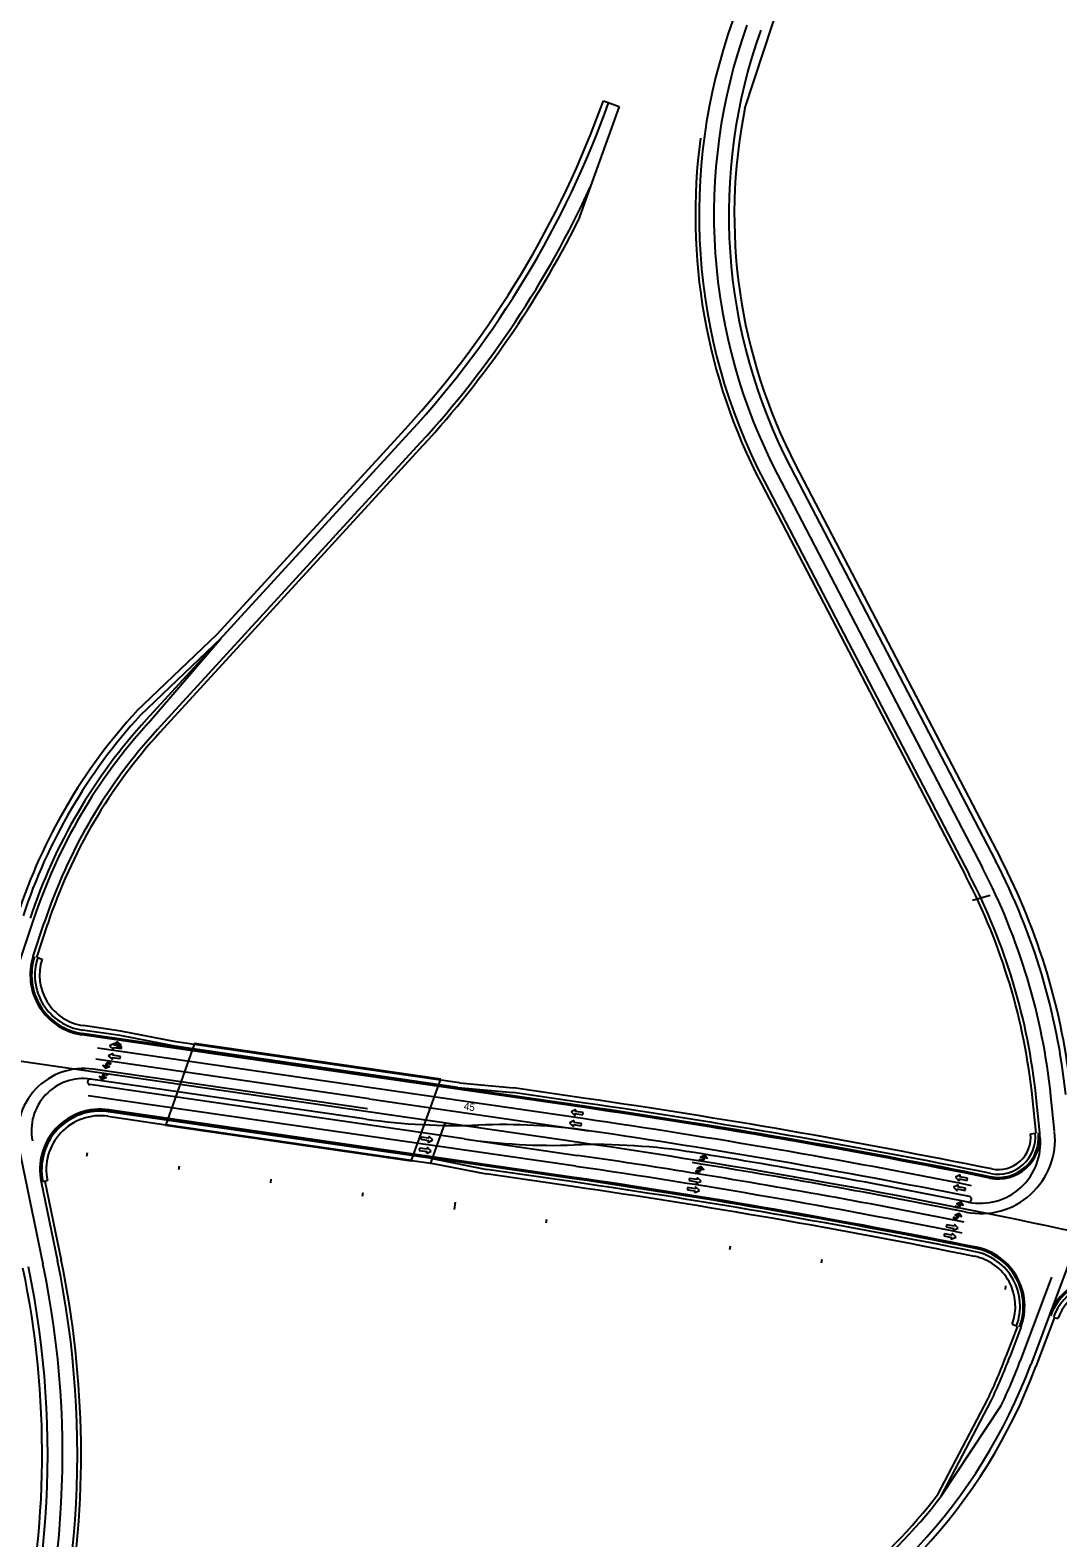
# Model space of a CAD drawing. Extents: x 1936748 to 1944587, y 778690 to 782840.
# Drawn here: x 1940638 to 1941746, y 780074 to 781699 of the extents above; entities that cross this region are included whole.
import ezdxf

# ---------------------------------------------------------------- set-up
doc = ezdxf.new("R2010")
doc.units = 0
for name, color, linetype in [('Default', 7, 'Continuous'), ('RD_HC_CL_Rel', 7, 'Continuous'), ('RD_HC_Data_Tic', 7, 'Continuous'), ('RD_HC_TX_Sta50', 7, 'Continuous'), ('RD_PD_ALT1_LnLine', 7, 'Continuous'), ('RD_PD_ALT3_LnLine', 7, 'Continuous'), ('RD_PD_Bridge', 7, 'Continuous'), ('RD_PD_Final_TrvlWay', 7, 'Continuous'), ('RD_PD_FOC', 7, 'Continuous'), ('RD_PD_PaveShd', 7, 'Continuous'), ('RD_PD_SW', 7, 'Continuous')]:
    doc.layers.add(name, color=color, linetype=linetype)

msp = doc.modelspace()

# ---------------------------------------------------------------- linework, layer by layer
at = {"layer": 'Default'}
for p, q in [((1940728.4, 780606.8), (1940723.9, 780604.6)), ((1940723.9, 780604.6), (1940727.5, 780601.2)), ((1940728.3, 780601.5), (1940728.1, 780602.8)), ((1940728.1, 780602.8), (1940736.6, 780601.6)), ((1940728.4, 780606.8), (1940728.4, 780606.8)), ((1940728.5, 780605.1), (1940728.9, 780606.3)), ((1940736.9, 780603.9), (1940728.5, 780605.1)), ((1940735.3, 780602.9), (1940736.6, 780602.8)), ((1940736.6, 780601.6), (1940736.9, 780603.9)), ((1940727.1, 780596), (1940722.6, 780593.8)), ((1940722.6, 780593.8), (1940726.3, 780590.4)), ((1940723.9, 780585.1), (1940725.2, 780584.9)), ((1940727, 780590.8), (1940726.9, 780592)), ((1940726.9, 780592), (1940735.3, 780590.8)), ((1940727.1, 780596), (1940727.1, 780596)), ((1940727.2, 780594.3), (1940727.7, 780595.5)), ((1940735.6, 780593.1), (1940727.2, 780594.3)), ((1940735.3, 780590.8), (1940735.6, 780593.1)), ((1940720.2, 780573.2), (1940721.6, 780573)), ((1941225.7, 780535.5), (1941221.3, 780533.3)), ((1941225.7, 780535.5), (1941225.7, 780535.5)), ((1941224, 780523.6), (1941219.5, 780521.4)), ((1941219.5, 780521.4), (1941223.2, 780518)), ((1941221.3, 780533.3), (1941224.9, 780529.9)), ((1941223.9, 780518.4), (1941223.8, 780519.6)), ((1941223.8, 780519.6), (1941232.2, 780518.4)), ((1941224, 780523.6), (1941224, 780523.6)), ((1941224.1, 780521.9), (1941224.6, 780523.1)), ((1941232.5, 780520.7), (1941224.1, 780521.9)), ((1941225.6, 780530.2), (1941225.5, 780531.5)), ((1941225.5, 780531.5), (1941233.9, 780530.3)), ((1941225.8, 780533.8), (1941226.3, 780535)), ((1941234.3, 780532.6), (1941225.8, 780533.8)), ((1941232.2, 780518.4), (1941232.5, 780520.7)), ((1941233.9, 780530.3), (1941234.3, 780532.6)), ((1941059.7, 780506.1), (1941059.4, 780503.8)), ((1941059.4, 780503.8), (1941067.8, 780502.6)), ((1941068.1, 780504.9), (1941059.7, 780506.1)), ((1941067.9, 780500.8), (1941072.4, 780503.1)), ((1941068, 780506.1), (1941068.1, 780504.9)), ((1941072.4, 780503.1), (1941068.7, 780506.5)), ((1941058, 780494.2), (1941057.6, 780491.9)), ((1941057.6, 780491.9), (1941066.1, 780490.7)), ((1941066.4, 780493), (1941058, 780494.2)), ((1941066.1, 780490.7), (1941065.6, 780489.5)), ((1941066.2, 780489), (1941070.6, 780491.2)), ((1941066.2, 780489), (1941066.2, 780489)), ((1941066.3, 780494.2), (1941066.4, 780493)), ((1941070.6, 780491.2), (1941067, 780494.6)), ((1941067.8, 780502.6), (1941067.3, 780501.4)), ((1941067.9, 780500.8), (1941067.9, 780500.8)), ((1941360.9, 780481.7), (1941359.5, 780481.9)), ((1941348.7, 780461.6), (1941348.4, 780459.3)), ((1941348.4, 780459.3), (1941356.8, 780458.1)), ((1941357.2, 780460.4), (1941348.7, 780461.6)), ((1941357.2, 780469.8), (1941355.9, 780470)), ((1941356.8, 780458.1), (1941356.4, 780456.9)), ((1941356.9, 780456.4), (1941361.4, 780458.6)), ((1941356.9, 780456.4), (1941356.9, 780456.4)), ((1941357, 780461.6), (1941357.2, 780460.4)), ((1941361.4, 780458.6), (1941357.8, 780462)), ((1941637.9, 780454.4), (1941633.4, 780452.3)), ((1941640, 780465.1), (1941635.5, 780463.1)), ((1941635.5, 780463.1), (1941638.9, 780459.5)), ((1941637.9, 780454.4), (1941637.9, 780454.4)), ((1941639.7, 780459.9), (1941639.6, 780461.1)), ((1941639.6, 780461.1), (1941648, 780459.5)), ((1941640, 780465.1), (1941640, 780465.1)), ((1941640, 780463.4), (1941640.6, 780464.6)), ((1941648.4, 780461.8), (1941640, 780463.4)), ((1941648, 780459.5), (1941648.4, 780461.8)), ((1941346.9, 780451.8), (1941346.6, 780449.5)), ((1941346.6, 780449.5), (1941355, 780448.3)), ((1941355.3, 780450.6), (1941346.9, 780451.8)), ((1941355, 780448.3), (1941354.5, 780447.1)), ((1941355.1, 780446.6), (1941359.6, 780448.8)), ((1941355.1, 780446.6), (1941355.1, 780446.6)), ((1941355.2, 780451.9), (1941355.3, 780450.6)), ((1941359.6, 780448.8), (1941355.9, 780452.2)), ((1941633.4, 780452.3), (1941636.9, 780448.8)), ((1941637.6, 780449.1), (1941637.5, 780450.4)), ((1941637.5, 780450.4), (1941645.9, 780448.8)), ((1941638, 780452.7), (1941638.5, 780453.8)), ((1941646.3, 780451.1), (1941638, 780452.7)), ((1941645.9, 780448.8), (1941646.3, 780451.1)), ((1941636.7, 780431.5), (1941635.3, 780431.8)), ((1941625.9, 780411.8), (1941625.5, 780409.5)), ((1941625.5, 780409.5), (1941633.8, 780407.8)), ((1941634.3, 780410.1), (1941625.9, 780411.8)), ((1941633.8, 780407.8), (1941633.3, 780406.6)), ((1941634.9, 780419.5), (1941633.5, 780419.8)), ((1941633.9, 780406.1), (1941638.4, 780408.1)), ((1941633.9, 780406.1), (1941633.9, 780406.1)), ((1941634.2, 780411.3), (1941634.3, 780410.1)), ((1941638.4, 780408.1), (1941635, 780411.7)), ((1941623.6, 780402.1), (1941623.1, 780399.8)), ((1941623.1, 780399.8), (1941631.5, 780398.1)), ((1941631.9, 780400.4), (1941623.6, 780402.1)), ((1941631.5, 780398.1), (1941631, 780397)), ((1941631.5, 780396.4), (1941636.1, 780398.4)), ((1941631.5, 780396.4), (1941631.5, 780396.4)), ((1941631.9, 780401.7), (1941631.9, 780400.4)), ((1941636.1, 780398.4), (1941632.6, 780402))]:
    msp.add_line(p, q, dxfattribs=at)
for points in [[(1940731.7, 780605.7), (1940731.8, 780606.8), (1940729.1, 780606.5), (1940732.4, 780608.7), (1940736, 780605.5), (1940733.5, 780606.6), (1940733.3, 780605.5)], [(1940736.6, 780602.8), (1940736.5, 780601.8), (1940734.5, 780602)], [(1940725.2, 780584.9), (1940725.4, 780585.9), (1940723.3, 780586.2)], [(1940716, 780571.5), (1940715.8, 780570.5), (1940713.3, 780571.6), (1940715.8, 780568.5), (1940720.2, 780570.5), (1940717.4, 780570.3), (1940717.6, 780571.3)], [(1940719.6, 780583.4), (1940719.4, 780582.4), (1940716.9, 780583.4), (1940719.5, 780580.4), (1940723.8, 780582.4), (1940721.1, 780582.1), (1940721.2, 780583.2)], [(1940721.6, 780573), (1940721.7, 780574), (1940719.7, 780574.3)], [(1941361.5, 780471.5), (1941361.6, 780472.5), (1941364.2, 780471.4), (1941361.6, 780474.5), (1941357.3, 780472.5), (1941360, 780472.7), (1941359.8, 780471.7)], [(1941359.5, 780481.9), (1941359.4, 780480.9), (1941361.4, 780480.6)], [(1941365.1, 780483.3), (1941365.3, 780484.4), (1941367.8, 780483.3), (1941365.3, 780486.4), (1941360.9, 780484.4), (1941363.6, 780484.6), (1941363.5, 780483.6)], [(1941355.9, 780470), (1941355.7, 780469), (1941357.7, 780468.7)], [(1941635.3, 780431.8), (1941635.1, 780430.8), (1941637.1, 780430.4)], [(1941639.2, 780420.9), (1941639.4, 780421.9), (1941641.9, 780420.7), (1941639.5, 780424), (1941635.1, 780422.2), (1941637.8, 780422.3), (1941637.6, 780421.3)], [(1941641, 780432.9), (1941641.2, 780434), (1941643.7, 780432.8), (1941641.3, 780436), (1941636.8, 780434.2), (1941639.6, 780434.3), (1941639.4, 780433.3)], [(1941633.5, 780419.8), (1941633.3, 780418.8), (1941635.3, 780418.4)]]:
    msp.add_lwpolyline(points, dxfattribs=at)
for centre, radius, start, end in [((1940727.8, 780601.5), 0.443, 226.7615, 7.2246), ((1940728.6, 780606.4), 0.443, 336.5504, 117.0366), ((1940734.9, 780605.3), 3.28, 172.1987, 262.1987), ((1940735.6, 780605.2), 2.3, 172.1987, 262.1987), ((1940722.8, 780582.9), 3.28, 81.3019, 171.3019), ((1940723.5, 780582.8), 2.3, 81.3019, 171.3019), ((1940726.6, 780590.7), 0.443, 226.7615, 7.2246), ((1940727.3, 780595.6), 0.443, 336.5504, 117.0366), ((1940719.2, 780571), 3.28, 81.3019, 171.3019), ((1940719.9, 780570.9), 2.3, 81.3019, 171.3019), ((1941225.9, 780535.1), 0.443, 336.5504, 117.0366), ((1941224.2, 780523.2), 0.443, 336.5504, 117.0366), ((1941225.2, 780530.2), 0.443, 226.7615, 7.2246), ((1941068.4, 780506.2), 0.443, 46.7615, 187.2246), ((1941223.5, 780518.3), 0.443, 226.7615, 7.2246), ((1941066, 780489.3), 0.443, 156.5504, 297.0366), ((1941066.7, 780494.3), 0.443, 46.7615, 187.2246), ((1941067.7, 780501.2), 0.443, 156.5504, 297.0366), ((1941357.6, 780472.1), 2.3, 261.3019, 351.3019), ((1941358.2, 780471.9), 3.28, 261.3019, 351.3019), ((1941361.2, 780483.9), 2.3, 261.3019, 351.3019), ((1941361.9, 780483.8), 3.28, 261.3019, 351.3019), ((1941356.7, 780456.7), 0.443, 156.5504, 297.0366), ((1941357.5, 780461.7), 0.443, 46.7615, 187.2246), ((1941638.1, 780454), 0.443, 334.1127, 114.5989), ((1941639.3, 780459.8), 0.443, 224.3238, 4.7869), ((1941640.2, 780464.7), 0.443, 334.1127, 114.5989), ((1941354.9, 780447), 0.443, 156.5504, 297.0366), ((1941355.6, 780451.9), 0.443, 46.7615, 187.2246), ((1941637.2, 780449.1), 0.443, 224.3238, 4.7869), ((1941637.1, 780433.8), 2.3, 258.1427, 348.1427), ((1941637.8, 780433.6), 3.28, 258.1427, 348.1427), ((1941633.7, 780406.5), 0.443, 153.3912, 293.8774), ((1941634.7, 780411.4), 0.443, 43.6023, 184.0654), ((1941635.3, 780421.7), 2.3, 258.1427, 348.1427), ((1941636, 780421.6), 3.28, 258.1427, 348.1427), ((1941631.3, 780396.8), 0.443, 153.3912, 293.8774), ((1941632.3, 780401.7), 0.443, 43.6023, 184.0654)]:
    msp.add_arc(centre, radius, start, end, dxfattribs=at)
at = {"layer": 'RD_HC_CL_Rel'}
for p, q in [((1940763.8, 780956.1), (1941047.3, 781265.4)), ((1941458, 781227.5), (1941678.6, 780803.9)), ((1941230.2, 780500.4), (1939659.5, 780728.1)), ((1941769.7, 780402.9), (1941716.6, 780260.9))]:
    msp.add_line(p, q, dxfattribs=at)
for centre, radius, start, end in [((1941981.2, 781500.1), 590, 160.2909, 207.5199), ((1940273.3, 781974.9), 1050, 317.4903, 340.2909), ((1941198.7, 780557.4), 590, 137.4903, 161.7503), ((1941057, 780480), 701, 5.9025, 27.5199), ((1940100.9, 772711.8), 7870, 74.0588, 81.7503), ((1939667.3, 780164.7), 990, 340.2909, 11.7503), ((1941164, 780467.7), 590, 294.3156, 339.4868)]:
    msp.add_arc(centre, radius, start, end, dxfattribs=at)
at = {"layer": 'RD_HC_Data_Tic'}
for p, q in [((1940699.6, 780485.5), (1940700.2, 780489.5)), ((1940798.6, 780471.2), (1940799.2, 780475.1)), ((1940897.6, 780456.8), (1940898.1, 780460.8)), ((1940996.5, 780442.5), (1940997.1, 780446.4)), ((1941095.5, 780428.1), (1941096.6, 780436)), ((1941194.4, 780413.7), (1941195, 780417.7)), ((1941392.4, 780385), (1941393, 780389)), ((1941491.3, 780370.7), (1941491.9, 780374.6)), ((1941689.3, 780342), (1941689.8, 780345.9))]:
    msp.add_line(p, q, dxfattribs=at)
at = {"layer": 'RD_PD_ALT1_LnLine'}
for p, q in [((1941443.8, 781220.1), (1941664.5, 780796.5)), ((1940766.1, 780952.7), (1940844.3, 781043.9)), ((1940610.5, 780644.9), (1940642.2, 780741)), ((1941233.9, 780526.1), (1940710.9, 780601.9)), ((1941003.7, 780547.4), (1940709.2, 780590.1)), ((1941002.1, 780536.5), (1940706.2, 780579.4)), ((1941226.5, 780474.7), (1940701, 780550.8)), ((1941003.7, 780547.4), (1941240.6, 780513)), ((1941742.3, 780512.4), (1941738.3, 780550.4)), ((1941106, 780504.3), (1941228.2, 780486.5)), ((1940625.7, 780496.9), (1940652.2, 780369.5)), ((1941739.1, 780355.4), (1941705.3, 780265.1)), ((1941620.1, 780119.3), (1941684.7, 780216.9))]:
    msp.add_line(p, q, dxfattribs=at)
for centre, radius, start, end in [((1941981.2, 781500.1), 606, 160.2909, 207.5199), ((1941198.7, 780557.4), 586, 137.5817, 161.7503), ((1941057, 780480), 685, 5.9025, 27.5199), ((1940696, 780508.9), 71.2, 81.7503, 191.7503), ((1940695.6, 780513.4), 55.8, 81.7503, 191.7503), ((1940100.9, 772711.8), 7896, 78.66478, 81.7503), ((1941662.9, 780503.7), 79.9, 258.6648, 5.9025), ((1941662.1, 780499.9), 65, 258.6648, 5.9025), ((1940100.9, 772711.8), 7844, 78.66478, 81.7503), ((1940100.9, 772711.8), 7856, 80.84886, 81.7503), ((1940100.9, 772711.8), 7867, 78.66478, 80.84886), ((1940100.9, 772711.8), 7856, 78.66478, 80.84886), ((1939667.3, 780164.7), 1006, 340.2909, 11.7503), ((1941164, 780467.7), 578, 334.2817, 339.4868)]:
    msp.add_arc(centre, radius, start, end, dxfattribs=at)
at = {"layer": 'RD_PD_ALT3_LnLine'}
for p, q in [((1941000.5, 780525.6), (1940703.6, 780568.7)), ((1941106, 780504.3), (1940702.8, 780562.7))]:
    msp.add_line(p, q, dxfattribs=at)
for centre, radius, start, end in [((1940703.2, 780565.7), 3, 81.7502, 261.7504), ((1941096.7, 781188.7), 670, 261.7503, 272.1469), ((1941146.9, 779849.6), 670, 81.9608, 92.1469), ((1941202.1, 781167.3), 670, 261.7503, 271.9334), ((1940100.9, 772711.8), 7884, 78.66478, 81.68895), ((1941247.3, 779828.1), 670, 80.8489, 91.9334), ((1940100.9, 772711.8), 7878, 78.66478, 80.84886), ((1941649.9, 780439.1), 3, 258.6644, 78.6651)]:
    msp.add_arc(centre, radius, start, end, dxfattribs=at)
at = {"layer": 'RD_PD_Bridge'}
for p, q in [((1940815.5, 780607), (1940784.3, 780518.6)), ((1941080.5, 780567.6), (1940815.1, 780606)), ((1941080.9, 780568.5), (1940815.5, 780607)), ((1941049.1, 780480.2), (1941080.9, 780568.5)), ((1941049.5, 780481.1), (1940784.6, 780519.5)), ((1941085.4, 780521.4), (1941069.5, 780477.2)), ((1941049.1, 780480.2), (1940784.3, 780518.6))]:
    msp.add_line(p, q, dxfattribs=at)
at = {"layer": 'RD_PD_Final_TrvlWay'}
for p, q in [((1941273.1, 781616.7), (1941229, 781493.8)), ((1941256.1, 781622.8), (1941273.1, 781616.7)), ((1940775.6, 780945.3), (1941059.1, 781254.6)), ((1941429.6, 781212.7), (1941650.3, 780789.1)), ((1940757.3, 780960.8), (1940844.3, 781043.9)), ((1941653.7, 780761.4), (1941672.9, 780766.9)), ((1940641.7, 780701.2), (1940653.6, 780737.2)), ((1941235.6, 780538), (1940694.1, 780616.5)), ((1941224.7, 780462.8), (1940723.1, 780535.5)), ((1941726.3, 780510.8), (1941722.4, 780548.8)), ((1940650.2, 780457.9), (1940667.9, 780372.8)), ((1941705.9, 780301), (1941694.1, 780269.3)), ((1941620.1, 780119.3), (1941673.9, 780222.1))]:
    msp.add_line(p, q, dxfattribs=at)
for centre, radius, start, end in [((1941981.2, 781500.1), 622, 160.2909, 207.5199), ((1940273.3, 781974.9), 1066, 317.4903, 335.3259), ((1941198.7, 780557.4), 598, 137.5817, 161.7503), ((1941198.7, 780557.4), 574, 137.4903, 161.7503), ((1941057, 780480), 669, 5.9025, 27.5199), ((1940703.5, 780680.8), 65, 161.7503, 261.7503), ((1940713.8, 780471.2), 65, 81.7503, 191.7503), ((1940100.9, 772711.8), 7908, 79.48683, 81.7503), ((1940100.9, 772711.8), 7908, 78.53622, 81.7503), ((1941681.6, 780506.2), 45, 258.5362, 5.9025), ((1940100.9, 772711.8), 7832, 78.5329, 81.7503), ((1941645.1, 780323.8), 65, 339.4868, 78.5329), ((1939667.3, 780164.7), 1022, 340.2909, 11.7503), ((1941797.3, 780291.3), 65, 77.2889, 159.4868), ((1941164, 780467.7), 566, 334.2817, 339.4868), ((1941164, 780467.7), 574, 294.3156, 322.6284)]:
    msp.add_arc(centre, radius, start, end, dxfattribs=at)
at = {"layer": 'RD_PD_FOC'}
for p, q in [((1941235.9, 780539.5), (1940694.4, 780618)), ((1941224.5, 780461.3), (1940722.9, 780534))]:
    msp.add_line(p, q, dxfattribs=at)
for centre, radius, start, end in [((1940703.5, 780680.8), 63.5, 161.7503, 261.7503), ((1940100.9, 772711.8), 7909.5, 78.53622, 81.7503), ((1940713.8, 780471.2), 63.5, 81.7503, 191.7503), ((1941681.6, 780506.2), 43.5, 258.5362, 5.9025), ((1940100.9, 772711.8), 7830.5, 78.47315, 81.7503), ((1941645.1, 780323.8), 63.5, 339.4868, 78.5329), ((1941797.3, 780291.3), 63.5, 77.2889, 159.4868)]:
    msp.add_arc(centre, radius, start, end, dxfattribs=at)
at = {"layer": 'RD_PD_PaveShd'}
for p, q in [((1941408.5, 781614.5), (1941528.9, 781981.1)), ((1940840, 781048.1), (1941042.9, 781269.4)), ((1940778.6, 780942.6), (1941062, 781251.9)), ((1941463.3, 781230.2), (1941684, 780806.7)), ((1941426, 781210.8), (1941646.7, 780787.3)), ((1940753, 780965), (1940840, 781048.1)), ((1940645.5, 780699.9), (1940657.4, 780735.9)), ((1941722.4, 780510.4), (1941718.4, 780548.4)), ((1940654.1, 780458.8), (1940671.8, 780373.6)), ((1941742.1, 780312), (1941722.2, 780258.8)), ((1941702.2, 780302.4), (1941690.3, 780270.7)), ((1941616.6, 780121.1), (1941670.4, 780223.9))]:
    msp.add_line(p, q, dxfattribs=at)
for centre, radius, start, end in [((1940273.3, 781974.9), 1044, 317.4903, 340.2909), ((1941981.2, 781500.1), 584, 168.7021, 207.5199), ((1941981.2, 781500.1), 626, 172.4312, 207.5199), ((1940273.3, 781974.9), 1070, 317.4903, 333.2802), ((1941198.7, 780557.4), 604, 137.5623, 161.7503), ((1941198.7, 780557.4), 570, 137.4903, 161.7503), ((1941057, 780480), 707, 5.9025, 27.5199), ((1941057, 780480), 665, 5.9025, 27.5199), ((1939667.3, 780164.7), 1026, 349.7669, 11.7503), ((1939667.3, 780164.7), 984, 347.209, 11.7503), ((1941164, 780467.7), 562, 334.2817, 339.4868), ((1941164, 780467.7), 596, 294.3156, 339.4868), ((1941164, 780467.7), 570, 294.3156, 322.6284)]:
    msp.add_arc(centre, radius, start, end, dxfattribs=at)
at = {"layer": 'RD_PD_SW'}
for p, q in [((1940646.5, 780699.6), (1940651.2, 780698.1)), ((1940735.5, 780615.6), (1940694.9, 780621.5)), ((1940736.3, 780620.5), (1940695.6, 780626.4)), ((1940795.4, 780608.9), (1940736.3, 780620.5)), ((1940794.4, 780604), (1940735.5, 780615.6)), ((1941099.2, 780559.8), (1940794.4, 780604)), ((1941100.9, 780564.6), (1940795.4, 780608.9)), ((1941099.2, 780559.8), (1941159, 780554.2)), ((1941100.9, 780564.6), (1941159.4, 780559.2)), ((1941236.5, 780542.9), (1941159, 780554.2)), ((1941237.3, 780547.9), (1941159.4, 780559.2)), ((1940722.1, 780528.6), (1940784.6, 780519.5)), ((1941071.6, 780483), (1940722.8, 780533.5)), ((1941716.4, 780509.8), (1941721.4, 780510.3)), ((1941049.5, 780481.1), (1941070.6, 780478.1)), ((1941069.9, 780478.2), (1941070.6, 780478.1)), ((1941070.6, 780478.1), (1941129.7, 780466.5)), ((1941071.6, 780483), (1941130.6, 780471.4)), ((1941224, 780457.8), (1941130.6, 780471.4)), ((1940652.1, 780458.4), (1940657, 780459.4)), ((1941223.3, 780452.9), (1941129.7, 780466.5)), ((1941741.1, 780312.3), (1941745.8, 780310.6)), ((1941696.6, 780304.5), (1941701.3, 780302.8))]:
    msp.add_line(p, q, dxfattribs=at)
for centre, radius, start, end in [((1940703.5, 780680.8), 60, 161.7503, 261.7503), ((1940703.5, 780680.8), 55, 161.7503, 261.7503), ((1940100.9, 772711.8), 7913, 78.53622, 81.7503), ((1940100.9, 772711.8), 7918, 78.53622, 81.7503), ((1940713.8, 780471.2), 63, 81.7503, 191.7503), ((1940713.8, 780471.2), 58, 81.7503, 191.7503), ((1941681.6, 780506.2), 40, 258.5362, 5.9025), ((1941681.6, 780506.2), 35, 258.5362, 5.9025), ((1940100.9, 772711.8), 7827, 78.5329, 81.7503), ((1940100.9, 772711.8), 7822, 78.5329, 81.7503), ((1941645.1, 780323.8), 55, 339.4868, 78.5329), ((1941645.1, 780323.8), 60, 339.4868, 78.5329), ((1941797.3, 780291.3), 60, 77.2889, 159.4868), ((1941797.3, 780291.3), 55, 77.2889, 159.4868)]:
    msp.add_arc(centre, radius, start, end, dxfattribs=at)

# ---------------------------------------------------------------- texts
at = {"layer": 'RD_HC_TX_Sta50'}
msp.add_text('45', height=8, rotation=351.7449, dxfattribs=at).set_placement((1941105.3, 780535.8))

doc.saveas('drawing.dxf')
